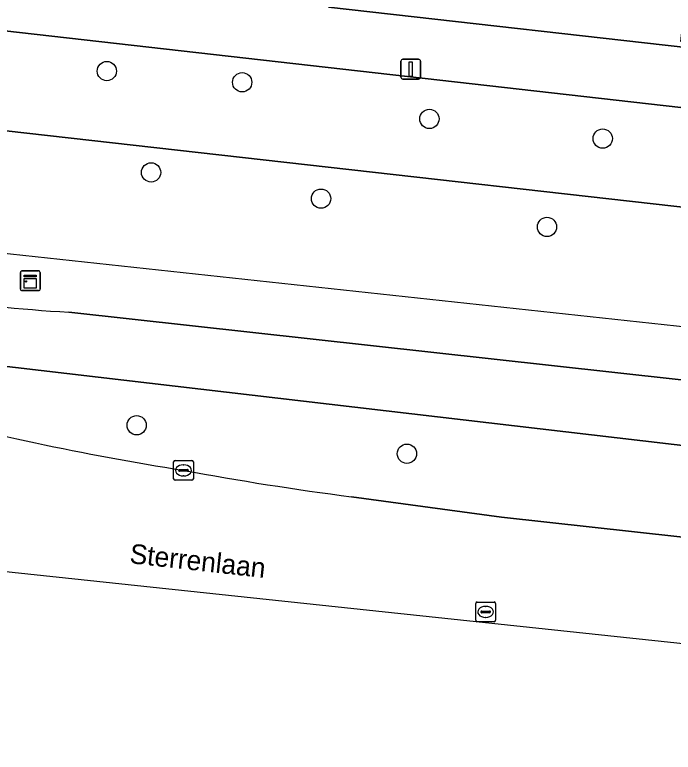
# Model space of a CAD drawing. Extents: x 161928 to 163071, y 386474 to 387428.
# Drawn here: x 162310.09 to 162343.49, y 386473.61 to 386511.04 of the extents above; entities that cross this region are included whole.
import ezdxf

# ---------------------------------------------------------------- set-up
doc = ezdxf.new("R2010")
doc.units = 0
for name, color, linetype in [('IMGEO_Berm_groen', 7, 'Continuous'), ('IMGEO_Boom', 7, 'Continuous'), ('IMGEO_Erf', 7, 'Continuous'), ('IMGEO_Fietspad_gesloten', 7, 'Continuous'), ('IMGEO_Gemengd_bos', 7, 'Continuous'), ('IMGEO_Groenvoorziening', 7, 'Continuous'), ('IMGEO_Kast', 7, 'Continuous'), ('IMGEO_Kolk', 7, 'Continuous'), ('IMGEO_Lichtmast', 7, 'Continuous'), ('IMGEO_Muur', 7, 'Continuous'), ('IMGEO_Openbare_ruimte_label', 7, 'Continuous'), ('IMGEO_Rijbaan_regionaal_gesloten', 7, 'Continuous'), ('IMGEO_Rioolput', 7, 'Continuous'), ('IMGEO_Voetpad_open', 7, 'Continuous')]:
    doc.layers.add(name, color=color, linetype=linetype)

msp = doc.modelspace()

# ---------------------------------------------------------------- linework, layer by layer
at = {"layer": 'IMGEO_Berm_groen'}
for points in [[(162401.944, 386482.942), (162401.205, 386483.023), (162399.009, 386483.265), (162393.815, 386483.838), (162367.735, 386486.526), (162350.052, 386488.472), (162306.2, 386493.586)], [(162327.176, 386486.572), (162334.785, 386485.54), (162398.255, 386478.536), (162398.388, 386478.521), (162399.012, 386478.452), (162401.944, 386482.942)]]:
    msp.add_lwpolyline(points, dxfattribs=at)
for centre, radius, start, end in [((162344.532, 386648.298), 162.46, 255.44098, 260.83344), ((162348.673, 386651.003), 165.83, 259.5695, 262.55152)]:
    msp.add_arc(centre, radius, start, end, dxfattribs=at)
at = {"layer": 'IMGEO_Boom'}
for centre in [(162314.76, 386508.177), (162321.628, 386507.609), (162331.125, 386505.75), (162339.916, 386504.751), (162317.006, 386503.034), (162325.627, 386501.703), (162337.09, 386500.268), (162316.274, 386490.202), (162329.984, 386488.759)]:
    msp.add_circle(centre, 0.489, dxfattribs=at)
at = {"layer": 'IMGEO_Erf'}
msp.add_lwpolyline([(162326.011, 386511.421), (162346.386, 386509.112), (162346.418, 386509.405), (162343.885, 386509.685), (162344.44, 386514.715), (162344.858, 386518.506), (162345.299, 386522.5), (162347.652, 386522.24), (162348.108, 386526.371), (162345.733, 386526.635), (162346.167, 386530.546)], dxfattribs=at)
at = {"layer": 'IMGEO_Fietspad_gesloten'}
for points in [[(162403.801, 386485.785), (162403.075, 386485.867), (162399.406, 386486.263), (162386.427, 386487.665), (162377.764, 386488.659), (162368.233, 386489.824), (162312.836, 386495.938)], [(162306.2, 386493.586), (162350.052, 386488.472), (162367.735, 386486.526), (162393.815, 386483.838), (162399.009, 386483.265), (162401.205, 386483.023), (162401.944, 386482.942), (162403.801, 386485.785)]]:
    msp.add_lwpolyline(points, dxfattribs=at)
msp.add_arc((162318.315, 386584.674), 88.905, 256.89915, 266.46689, dxfattribs=at)
at = {"layer": 'IMGEO_Gemengd_bos'}
msp.add_lwpolyline([(162297.494, 386506.509), (162370.953, 386498.22), (162371.516, 386503.188), (162347.162, 386505.951), (162298.087, 386511.519)], close=True, dxfattribs=at)
at = {"layer": 'IMGEO_Groenvoorziening'}
for points in [[(162380.871, 386491.346), (162381.458, 386496.265), (162381.983, 386500), (162382.205, 386501.975), (162371.516, 386503.188), (162370.953, 386498.22), (162297.494, 386506.509), (162297.39, 386505.635), (162272.624, 386508.235), (162272.737, 386509.296), (162259.637, 386510.771), (162256.748, 386511.459), (162243.789, 386512.877), (162224.131, 386515.029), (162212.87, 386516.261), (162203.272, 386522.117), (162202.401, 386522.176), (162203.943, 386517.405), (162205.389, 386517.222), (162205.323, 386515.589), (162212.718, 386514.865), (162249.57, 386510.502)], [(162312.836, 386495.938), (162368.233, 386489.824), (162377.764, 386488.659)]]:
    msp.add_lwpolyline(points, dxfattribs=at)
msp.add_arc((162318.315, 386584.674), 88.905, 256.89915, 266.46689, dxfattribs=at)
at = {"layer": 'IMGEO_Kast'}
for p, q in [((162310.377, 386497.112), (162310.377, 386497.953)), ((162310.377, 386497.953), (162310.377, 386497.112)), ((162310.452, 386498.037), (162311.293, 386498.037)), ((162311.293, 386498.037), (162310.452, 386498.037)), ((162311.377, 386497.962), (162311.377, 386497.121)), ((162311.377, 386497.121), (162311.377, 386497.962)), ((162311.302, 386497.037), (162310.461, 386497.037)), ((162310.461, 386497.037), (162311.302, 386497.037))]:
    msp.add_line(p, q, dxfattribs=at)
for points in [[(162310.572, 386497.827), (162311.172, 386497.827), (162311.172, 386497.742), (162310.572, 386497.742), (162310.572, 386497.827)], [(162310.572, 386497.652), (162311.172, 386497.652), (162311.172, 386497.163), (162310.572, 386497.163), (162310.572, 386497.652)]]:
    msp.add_lwpolyline(points, dxfattribs=at)
msp.add_circle((162310.656, 386497.501), 0.0377, dxfattribs=at)
for centre, start, end in [((162310.455, 386497.959), 92.4484, 184.2845), ((162310.455, 386497.959), 92.4484, 184.2845), ((162311.299, 386497.959), 2.4484, 94.2845), ((162311.299, 386497.959), 2.4484, 94.2845), ((162310.455, 386497.115), 182.4484, 274.2845), ((162310.455, 386497.115), 182.4484, 274.2845), ((162311.299, 386497.115), 272.4484, 4.2845), ((162311.299, 386497.115), 272.4484, 4.2845)]:
    msp.add_arc(centre, 0.0779, start, end, dxfattribs=at)
at = {"layer": 'IMGEO_Kolk'}
for p, q in [((162318.15, 386487.487), (162318.15, 386488.339)), ((162318.225, 386488.413), (162319.077, 386488.413)), ((162319.151, 386488.339), (162319.151, 386487.487)), ((162318.409, 386487.907), (162318.409, 386487.919)), ((162318.847, 386487.87), (162318.449, 386487.87)), ((162318.452, 386487.956), (162318.85, 386487.956)), ((162318.638, 386488.193), (162318.663, 386488.193)), ((162318.893, 386487.919), (162318.893, 386487.907)), ((162318.661, 386487.633), (162318.636, 386487.633)), ((162319.077, 386487.413), (162318.225, 386487.413))]:
    msp.add_line(p, q, dxfattribs=at)
for points in [[(162318.15, 386487.487), (162318.15, 386488.339)], [(162318.225, 386488.413), (162319.077, 386488.413)], [(162319.151, 386488.339), (162319.151, 386487.487)], [(162319.077, 386487.413), (162318.225, 386487.413)]]:
    msp.add_lwpolyline(points, dxfattribs=at)
for centre, radius, start, end in [((162318.227, 386488.337), 0.0765, 91.552, 178.448), ((162318.227, 386488.337), 0.0765, 91.552, 178.448), ((162319.075, 386488.337), 0.0765, 1.552, 88.448), ((162319.075, 386488.337), 0.0765, 1.552, 88.448), ((162318.449, 386487.916), 0.0403, 85.8775, 175.7526), ((162318.446, 386487.906), 0.0366, 178.938, 274.7102), ((162318.85, 386487.913), 0.043, 264.8664, 352.4533), ((162318.854, 386487.918), 0.0386, 1.7309, 96.639), ((162318.227, 386487.489), 0.0765, 181.552, 268.448), ((162318.227, 386487.489), 0.0765, 181.552, 268.448), ((162319.075, 386487.489), 0.0765, 271.552, 358.448), ((162319.075, 386487.489), 0.0765, 271.552, 358.448)]:
    msp.add_arc(centre, radius, start, end, dxfattribs=at)
for centre, major_axis, ratio, start_param, end_param in [((162318.637, 386487.913), (-0.387, 0.002), 0.722429, 4.712389, 7.853982), ((162318.662, 386487.913), (-0.39, 0.002), 0.717154, 1.570796, 4.712389)]:
    msp.add_ellipse(centre, major_axis=major_axis, ratio=ratio, start_param=start_param, end_param=end_param, dxfattribs=at)
at = {"layer": 'IMGEO_Lichtmast'}
for p, q in [((162329.683, 386507.874), (162329.683, 386508.674)), ((162329.683, 386508.674), (162329.683, 386507.874)), ((162329.783, 386508.774), (162330.573, 386508.774)), ((162330.573, 386508.774), (162329.783, 386508.774)), ((162330.673, 386508.674), (162330.673, 386507.874)), ((162330.673, 386507.874), (162330.673, 386508.674)), ((162330.573, 386507.774), (162329.783, 386507.774)), ((162329.783, 386507.774), (162330.573, 386507.774))]:
    msp.add_line(p, q, dxfattribs=at)
msp.add_lwpolyline([(162330.103, 386508.649), (162330.253, 386508.649), (162330.253, 386507.899), (162330.103, 386507.899), (162330.103, 386508.649)], dxfattribs=at)
for centre, start, end in [((162329.783, 386508.674), 90, 180), ((162329.783, 386508.674), 90, 180), ((162330.573, 386508.674), 0, 90), ((162330.573, 386508.674), 360, 90), ((162329.783, 386507.874), 180, 270), ((162329.783, 386507.874), 180, 270), ((162330.573, 386507.874), 270, 0), ((162330.573, 386507.874), 270, 0)]:
    msp.add_arc(centre, 0.1, start, end, dxfattribs=at)
at = {"layer": 'IMGEO_Muur'}
msp.add_lwpolyline([(162380.469, 386495.521), (162368.68, 386492.53), (162309.226, 386498.961), (162259.637, 386510.771)], dxfattribs=at)
at = {"layer": 'IMGEO_Rijbaan_regionaal_gesloten'}
for points in [[(162270.084, 386488.203), (162257.775, 386488.3), (162395.849, 386473.608)], [(162395.849, 386473.608), (162398.218, 386477.235), (162398.388, 386478.521), (162398.255, 386478.536), (162334.785, 386485.54), (162327.176, 386486.572)]]:
    msp.add_lwpolyline(points, dxfattribs=at)
for centre, radius, start, end in [((162344.532, 386648.298), 162.46, 255.44098, 260.83344), ((162348.673, 386651.003), 165.83, 259.5695, 262.55152)]:
    msp.add_arc(centre, radius, start, end, dxfattribs=at)
at = {"layer": 'IMGEO_Rioolput'}
for p, q in [((162333.477, 386480.307), (162333.477, 386481.159)), ((162333.552, 386481.233), (162334.404, 386481.233)), ((162334.478, 386481.159), (162334.478, 386480.307)), ((162333.736, 386480.727), (162333.736, 386480.739)), ((162333.779, 386480.776), (162334.177, 386480.776)), ((162333.965, 386481.013), (162333.99, 386481.013)), ((162334.22, 386480.739), (162334.22, 386480.727)), ((162334.174, 386480.69), (162333.776, 386480.69)), ((162333.988, 386480.453), (162333.963, 386480.453)), ((162334.404, 386480.233), (162333.552, 386480.233))]:
    msp.add_line(p, q, dxfattribs=at)
for points in [[(162333.477, 386480.307), (162333.477, 386481.159)], [(162333.552, 386481.233), (162334.404, 386481.233)], [(162334.478, 386481.159), (162334.478, 386480.307)], [(162334.404, 386480.233), (162333.552, 386480.233)]]:
    msp.add_lwpolyline(points, dxfattribs=at)
for centre, radius, start, end in [((162333.554, 386481.157), 0.0765, 91.552, 178.448), ((162333.554, 386481.157), 0.0765, 91.552, 178.448), ((162334.402, 386481.157), 0.0765, 1.552, 88.448), ((162334.402, 386481.157), 0.0765, 1.552, 88.448), ((162333.776, 386480.736), 0.0403, 85.8775, 175.7526), ((162333.773, 386480.726), 0.0366, 178.938, 274.7102), ((162334.177, 386480.733), 0.043, 264.8664, 352.4533), ((162334.181, 386480.738), 0.0386, 1.7309, 96.639), ((162333.554, 386480.309), 0.0765, 181.552, 268.448), ((162333.554, 386480.309), 0.0765, 181.552, 268.448), ((162334.402, 386480.309), 0.0765, 271.552, 358.448), ((162334.402, 386480.309), 0.0765, 271.552, 358.448)]:
    msp.add_arc(centre, radius, start, end, dxfattribs=at)
for centre, major_axis, ratio, start_param, end_param in [((162333.964, 386480.733), (-0.387, 0.002), 0.722429, 4.712389, 7.853982), ((162333.989, 386480.733), (-0.39, 0.002), 0.717154, 1.570796, 4.712389)]:
    msp.add_ellipse(centre, major_axis=major_axis, ratio=ratio, start_param=start_param, end_param=end_param, dxfattribs=at)
at = {"layer": 'IMGEO_Voetpad_open'}
msp.add_lwpolyline([(162245.671, 386520.399), (162225.221, 386522.702), (162223.909, 386522.85), (162201.776, 386525.342), (162202.401, 386522.176), (162203.272, 386522.117), (162210.364, 386521.35), (162224.653, 386519.735), (162244.314, 386517.547), (162273.275, 386514.324), (162298.087, 386511.519), (162347.162, 386505.951), (162371.516, 386503.188), (162382.205, 386501.975), (162382.604, 386505.469), (162378.144, 386505.94), (162375.565, 386506.213), (162368.502, 386506.62), (162368.281, 386506.633), (162347.875, 386508.944), (162346.386, 386509.112), (162326.011, 386511.421)], dxfattribs=at)

# ---------------------------------------------------------------- texts
at = {"layer": 'IMGEO_Openbare_ruimte_label'}
msp.add_text('Sterrenlaan', height=1, rotation=353.7421, dxfattribs=at).set_placement((162315.884, 386483.205))

doc.saveas('drawing.dxf')
